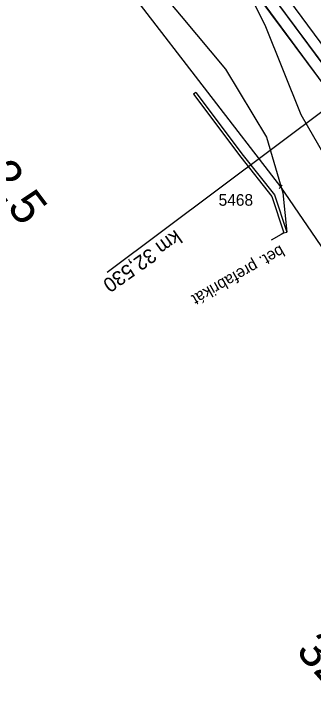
# Model space of a CAD drawing. Extents: x -804166 to -803706, y -1151030 to -1150147.
# Drawn here: x -804080 to -804028.2, y -1150435.2 to -1150318 of the extents above; entities that cross this region are included whole.
import ezdxf

# ---------------------------------------------------------------- set-up
doc = ezdxf.new("R2010")
doc.units = 0
for name, color, linetype in [('0381KM032-037P - Vrstva 1', 7, 'Continuous'), ('0381KM032-037P - Vrstva 13', 7, 'Continuous'), ('0381KM032-037P - Vrstva 41', 7, 'Continuous'), ('0381KM032-037P - Vrstva 49', 7, 'Continuous'), ('0381KM032-037P - Vrstva 7', 7, 'Continuous'), ('DZ_CD - CD', 7, 'Continuous'), ('szdc - hran DP', 7, 'Continuous'), ('szdc - szdc_cislo', 7, 'Continuous'), ('szdc - szdc_krizek', 7, 'Continuous'), ('VB - VB', 7, 'Continuous')]:
    doc.layers.add(name, color=color, linetype=linetype)

msp = doc.modelspace()

# ---------------------------------------------------------------- linework, layer by layer
at = {"layer": '0381KM032-037P - Vrstva 1'}
msp.add_lwpolyline([(-804088.45, -1150239.45), (-804070.36, -1150264.07), (-804054.98, -1150285.05), (-804052.95, -1150287.79), (-804037.56, -1150308.64), (-804021.87, -1150329.91), (-804004.48, -1150353.56), (-803990.76, -1150372.09)], dxfattribs=at)
at = {"layer": '0381KM032-037P - Vrstva 13'}
for p, q in [((-804040.72, -1150342.79), (-804035.37, -1150349.53)), ((-804035.37, -1150349.53), (-804033.33, -1150355.83)), ((-804033.33, -1150355.83), (-804032.83, -1150355.72))]:
    msp.add_line(p, q, dxfattribs=at)
for points in [[(-804048.5, -1150331.59), (-804048.9, -1150331.9), (-804040.72, -1150342.79)], [(-804048.5, -1150331.59), (-804040.34, -1150342.47), (-804034.91, -1150349.29), (-804032.83, -1150355.72)], [(-804033.33, -1150355.83), (-804033.81, -1150356.11), (-804035.52, -1150357.08)]]:
    msp.add_lwpolyline(points, dxfattribs=at)
at = {"layer": '0381KM032-037P - Vrstva 41'}
msp.add_line((-804063.79, -1150362.63), (-804007.63, -1150320.5), dxfattribs=at)
at = {"layer": '0381KM032-037P - Vrstva 49'}
for points in [[(-804119.6, -1150227.37), (-804114.18, -1150233.24), (-804110.61, -1150241.24), (-804107.35, -1150246.09), (-804099.61, -1150256.67), (-804091.21, -1150269.57), (-804073.78, -1150287.54), (-804061.47, -1150301.24), (-804053.54, -1150315.4), (-804051.02, -1150318.44), (-804043.41, -1150327.56), (-804036.34, -1150339.31), (-804033.47, -1150348.91), (-804032.83, -1150355.72)], [(-804067.58, -1150273.2), (-804053.47, -1150291.61), (-804044.04, -1150305.1), (-804036.58, -1150319.92), (-804030.41, -1150335.37), (-804026.23, -1150342.57), (-804022.74, -1150350.54)]]:
    msp.add_lwpolyline(points, dxfattribs=at)
at = {"layer": 'DZ_CD - CD'}
for p, q in [((-804042.88, -1150308), (-804006.89, -1150356.88)), ((-804005.25, -1150355.72), (-804040.67, -1150307.63))]:
    msp.add_line(p, q, dxfattribs=at)
at = {"layer": 'szdc - hran DP'}
for p, q in [((-804033.86, -1150347.88), (-804060.01, -1150313.9)), ((-804004.05, -1150391.51), (-804033.86, -1150347.88))]:
    msp.add_line(p, q, dxfattribs=at)
at = {"layer": 'szdc - szdc_krizek'}
for p, q in [((-804033.59, -1150348.15), (-804034.13, -1150347.61)), ((-804034.13, -1150348.15), (-804033.59, -1150347.61))]:
    msp.add_line(p, q, dxfattribs=at)
at = {"layer": 'VB - VB'}
for p, q in [((-804078.87, -1150259.13), (-804006.89, -1150356.88)), ((-804076.08, -1150259.54), (-804005.25, -1150355.72))]:
    msp.add_line(p, q, dxfattribs=at)

# ---------------------------------------------------------------- texts
at = {"layer": '0381KM032-037P - Vrstva 13'}
msp.add_text('bet. prefabrikát', height=2, rotation=209.6616, dxfattribs=at).set_placement((-804033.92, -1150357.9))
at = {"layer": '0381KM032-037P - Vrstva 41'}
msp.add_text('km 32,530', height=2.5, rotation=215.4715, dxfattribs=at).set_placement((-804052.06, -1150355.2))
at = {"layer": '0381KM032-037P - Vrstva 7'}
for s, rotation, p in [('32,5', 306.9651, (-804087.92, -1150342.46)), ('32,6', 311.8828, (-804031.4, -1150428.19))]:
    msp.add_text(s, height=6, rotation=rotation, dxfattribs=at).set_placement(p)
at = {"layer": 'szdc - szdc_cislo'}
msp.add_text('5468', height=2, dxfattribs=at).set_placement((-804044.58, -1150351.15))

doc.saveas('drawing.dxf')
